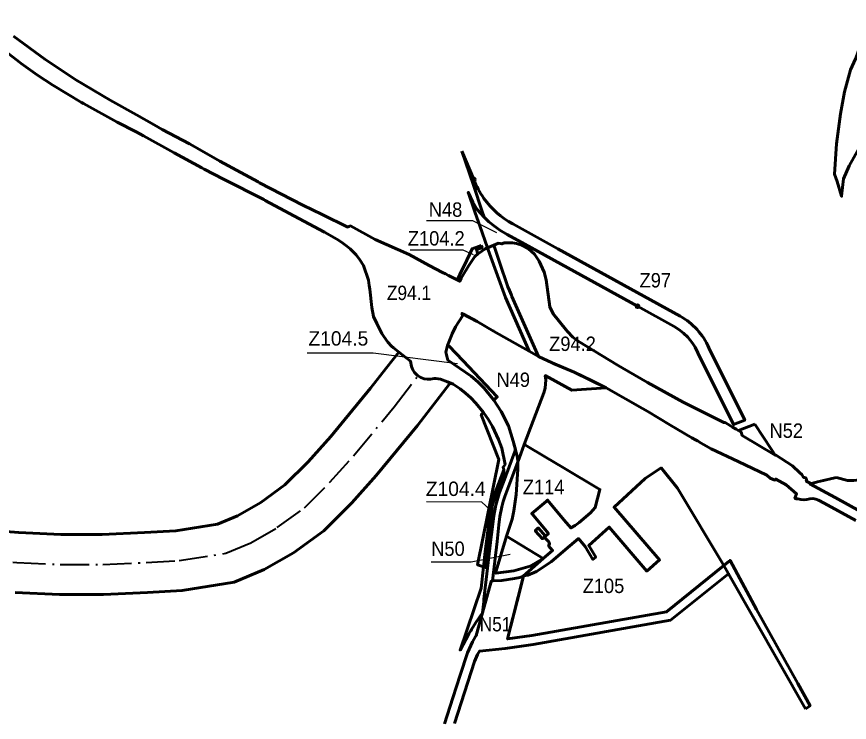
# Model space of a CAD drawing. Extents: x -650277 to -643425, y -1073980 to -1066720.
# Drawn here: x -647342 to -645952, y -1069308 to -1068130 of the extents above; entities that cross this region are included whole.
import ezdxf

# ---------------------------------------------------------------- set-up
doc = ezdxf.new("R2010")
doc.units = 0
doc.header["$LTSCALE"] = 9.6
doc.header["$PDMODE"] = 32
doc.header["$PDSIZE"] = 4.8
doc.linetypes.add('DOT_DASHED', pattern=[7.7, 5, -1.2, 0.3, -1.2])
for name, color, linetype, lineweight in [('15', 7, 'Continuous', 60), ('24', 7, 'Continuous', 60), ('30', 7, 'Continuous', 60), ('34', 7, 'Continuous', 60), ('36', 7, 'Continuous', 60), ('42', 7, 'Continuous', 60), ('48', 7, 'Continuous', 60), ('60', 7, 'Continuous', 60), ('62', 7, 'DOT_DASHED', 40), ('63', 7, 'Continuous', 25), ('7', 7, 'Continuous', 60)]:
    doc.layers.add(name, color=color, linetype=linetype, lineweight=lineweight)

msp = doc.modelspace()

# ---------------------------------------------------------------- linework, layer by layer
at = {"layer": '15'}
for points in [[(-646037.99, -1069242.88), (-646107, -1069119.41), (-646150.87, -1069037.64), (-646152.26, -1069038.76), (-646161.484, -1069046.228), (-646153.307, -1069059.947), (-646025.14, -1069285.394)], [(-646025.14, -1069285.394), (-646017.15, -1069280.19), (-646037.99, -1069242.88)]]:
    msp.add_lwpolyline(points, dxfattribs=at)
at = {"layer": '24'}
for points in [[(-646562.49, -1068790.69), (-646566.34, -1068794.32), (-646537.3, -1068868.95), (-646572.42, -1069044.94), (-646562.61, -1069048.08)], [(-646526.64, -1068877.47), (-646532.16, -1068850.47), (-646537.35, -1068835.56), (-646547.68, -1068814.22), (-646554.8, -1068801.98), (-646562.49, -1068790.69)], [(-646562.61, -1069048.08), (-646561.134, -1069035.627), (-646560.79, -1069032.72), (-646560.2, -1069027.69), (-646555.62, -1068988.63), (-646555, -1068983.32), (-646550.3, -1068943.27), (-646537.69, -1068909.82), (-646528.92, -1068886.55)], [(-646528.92, -1068886.55), (-646530.06, -1068882.16), (-646526.64, -1068877.47)], [(-646555.84, -1069050.22), (-646550.89, -1069007.7), (-646549.81, -1068998.88), (-646549.17, -1068993.71), (-646545.42, -1068963.3), (-646542.16, -1068945.12), (-646536.54, -1068925.95), (-646533.28, -1068917.17), (-646529.44, -1068906.81), (-646529.146, -1068895.373), (-646529.36, -1068895.94), (-646535.79, -1068912.99), (-646547.46, -1068943.97), (-646552.58, -1068987.63), (-646553.2, -1068992.9), (-646556.02, -1069016.97), (-646557.96, -1069033.47), (-646558.145, -1069035.029)], [(-646558.145, -1069035.029), (-646559.8, -1069048.98), (-646555.84, -1069050.22)]]:
    msp.add_lwpolyline(points, dxfattribs=at)
at = {"layer": '30'}
msp.add_line((-646583.49, -1068729.76), (-646571.91, -1068739.54), dxfattribs=at)
for points in [[(-646566.33, -1068512.04), (-646581.64, -1068517.24), (-646590.31, -1068536.69), (-646602.01, -1068560.15), (-646606.59, -1068569.33)], [(-646587.28, -1068545.28), (-646577.07, -1068530.2), (-646572.02, -1068526.07), (-646574.48, -1068518.75), (-646565.04, -1068515.86), (-646566.33, -1068512.04)], [(-646599.75, -1068566.49), (-646587.28, -1068545.28), (-646587.28, -1068545.28)], [(-646606.59, -1068569.33), (-646602.21, -1068571.5), (-646599.75, -1068566.49)], [(-646571.91, -1068739.54), (-646561.5, -1068750.22), (-646545.32, -1068769.89), (-646539.78, -1068764.65), (-646596.93, -1068704.15), (-646619.74, -1068680.15), (-646622.68, -1068678.75), (-646625.35, -1068689.7)], [(-646625.35, -1068689.7), (-646622.01, -1068703.3), (-646583.49, -1068729.76)]]:
    msp.add_lwpolyline(points, dxfattribs=at)
at = {"layer": '34'}
msp.add_lwpolyline([(-646161.484, -1069046.228), (-646238.632, -1068916.799), (-646266.118, -1068883.048), (-646277.268, -1068890.446), (-646292.75, -1068900.72), (-646344.49, -1068948.736), (-646268.528, -1069036.82), (-646290.099, -1069055.423), (-646352.71, -1068981.82), (-646386.936, -1069012.936), (-646375.346, -1069032.07), (-646379.973, -1069035.889), (-646393.09, -1069014.234), (-646404.269, -1069001.033), (-646425.52, -1069019.41), (-646449.418, -1069039.804), (-646474.13, -1069055.83), (-646488.537, -1069062.169), (-646495.89, -1069063.531), (-646500.995, -1069083.812), (-646522.35, -1069168.648), (-646482.211, -1069162.813), (-646256.824, -1069123.414)], close=True, dxfattribs=at)
at = {"layer": '36'}
msp.add_lwpolyline([(-646512.07, -1068954.68), (-646507.91, -1068927.47), (-646505.12, -1068885.31), (-646505.17, -1068872.78), (-646503.24, -1068867.61), (-646494.52, -1068844.29), (-646492.73, -1068845.01), (-646457.86, -1068865.8), (-646430.86, -1068881.89), (-646368.3, -1068919.19), (-646376.02, -1068949.34), (-646383.86, -1068958.24), (-646403.13, -1068974.41), (-646409.67, -1068979.3), (-646416.71, -1068983.21), (-646427.77, -1068970.39), (-646455.78, -1068936.87), (-646458.21, -1068938.99), (-646482.2, -1068959.52), (-646454.21, -1068992.73), (-646459.25, -1068996.98), (-646471.24, -1068983.41), (-646476.35, -1068987.98), (-646464.24, -1069001.49), (-646461.29, -1068998.81), (-646453.48, -1069006.75), (-646452.37, -1069010.01), (-646453.88, -1069013.1), (-646447.2, -1069020.9), (-646462.98, -1069034.61), (-646524, -1068997), (-646514.91, -1068968.48), (-646514.91, -1068968.48)], close=True, dxfattribs=at)
at = {"layer": '42'}
for points in [[(-646561.544, -1068464.842), (-646572.984, -1068451.81), (-646580.625, -1068439.803), (-646588.07, -1068422.96), (-646576.4, -1068457.27), (-646568.87, -1068479.14), (-646556.22, -1068515.84), (-646545.57, -1068511.42), (-646537.71, -1068508.16)], [(-646523.105, -1068493.54), (-646535.245, -1068486.342), (-646544.525, -1068479.79), (-646553.677, -1068472.283), (-646561.544, -1068464.842)], [(-646537.71, -1068508.16), (-646531.9, -1068509.25), (-646528.18, -1068507.58), (-646514.39, -1068507.56), (-646507.4, -1068508.45), (-646498.48, -1068511.26), (-646495.416, -1068512.888), (-646493.511, -1068509.855), (-646523.105, -1068493.54)], [(-646075.56, -1068861.95), (-646130.68, -1068829.21), (-646132.62, -1068823.54), (-646136.99, -1068820.88), (-646109.35, -1068810.23)], [(-646109.35, -1068810.23), (-646081.72, -1068852.51), (-646075.56, -1068861.95)], [(-646017.55, -1068909.75), (-646010.48, -1068907.86), (-646004.88, -1068906.5), (-645994.9, -1068904.1), (-645980.93, -1068900.85), (-645973.36, -1068898.93)], [(-645973.36, -1068898.93), (-645954.59, -1068904.41), (-645944.23, -1068904.13), (-645930.1, -1068902.47), (-645915.61, -1068901.02), (-645902.91, -1068901.43), (-645882.63, -1068905.88), (-645856.26, -1068997.79)], [(-645856.26, -1068997.79), (-645892.77, -1068977.86), (-645933.28, -1068955.74), (-645975.31, -1068932.8), (-646017.55, -1068909.75)]]:
    msp.add_lwpolyline(points, dxfattribs=at)
for points in [[(-646609.7, -1068647.84), (-646615.19, -1068659.11), (-646622.68, -1068678.75), (-646619.74, -1068680.15), (-646596.93, -1068704.15), (-646539.78, -1068764.65), (-646545.32, -1068769.89), (-646532.92, -1068788.95), (-646521.18, -1068812.95), (-646513.27, -1068838.37), (-646505.69, -1068865.56), (-646505.17, -1068872.78), (-646503.24, -1068867.61), (-646494.52, -1068844.29), (-646479.45, -1068804.37), (-646461.92, -1068757.93), (-646459.59, -1068750.19), (-646458.57, -1068736.31), (-646459.54, -1068728.94), (-646453.51, -1068732.3), (-646415.3, -1068753.62), (-646357.87, -1068749.64), (-646411.3, -1068723.11), (-646448.02, -1068707.99), (-646470.65, -1068697.38), (-646486.23, -1068688.54), (-646501.64, -1068679.81), (-646545.73, -1068654.81), (-646573.14, -1068638.98), (-646598.59, -1068625.34), (-646597.4, -1068628.74)], [(-646541.71, -1069054.76), (-646542, -1069059), (-646512, -1069055), (-646485, -1069047), (-646462.98, -1069034.61), (-646524, -1068997)]]:
    msp.add_lwpolyline(points, close=True, dxfattribs=at)
at = {"layer": '48'}
msp.add_lwpolyline([(-645874.15, -1068234.44), (-645917.44, -1068129.99), (-645938.87, -1068193.06), (-645941.41, -1068200.54), (-645949.52, -1068218.72), (-645959.76, -1068255.23), (-645966.56, -1068292.38), (-645973.25, -1068342.08), (-645976.63, -1068393.14), (-645971.94, -1068405.38), (-645964.53, -1068429.83), (-645963.12, -1068415.21), (-645961.7, -1068400.54), (-645952.21, -1068378.95), (-645926.06, -1068332.18), (-645883.87, -1068256.88), (-645880.28, -1068250.47), (-645872.64, -1068238.08)], close=True, dxfattribs=at)
at = {"layer": '60'}
msp.add_line((-646578.881, -1068401.54), (-646598.635, -1068354.436), dxfattribs=at)
for points in [[(-647419.713, -1068138.871), (-647405.71, -1068151.74), (-647372.38, -1068179.01), (-647337.74, -1068205.67), (-647334.62, -1068208.02), (-647307.39, -1068227.44), (-647281.64, -1068244.34), (-647234.11, -1068273.04), (-647230.83, -1068274.93), (-647174.56, -1068306.35), (-647142.788, -1068322.462), (-647130.29, -1068328.8), (-647079.16, -1068357.01), (-647032.91, -1068382.51), (-647029.23, -1068384.46), (-646997.06, -1068401.37), (-646929.56, -1068435.42), (-646927.06, -1068436.66)], [(-646634.37, -1068735.27), (-646622.62, -1068739.32), (-646613.44, -1068743.65), (-646601.86, -1068751.01), (-646592.53, -1068758.66), (-646583.98, -1068766.42), (-646575.28, -1068775.04), (-646562.49, -1068790.69), (-646554.8, -1068801.98), (-646547.68, -1068814.22), (-646537.35, -1068835.56), (-646532.16, -1068850.47), (-646526.64, -1068877.47), (-646530.06, -1068882.16), (-646528.92, -1068886.55), (-646529.44, -1068906.81), (-646510.56, -1068855.86), (-646509.323, -1068852.529), (-646513.27, -1068838.37), (-646521.18, -1068812.95), (-646532.92, -1068788.95), (-646545.32, -1068769.89), (-646561.5, -1068750.22), (-646571.91, -1068739.54), (-646583.49, -1068729.76), (-646622.01, -1068703.3), (-646625.35, -1068689.7), (-646622.68, -1068678.75), (-646615.19, -1068659.11), (-646609.7, -1068647.84), (-646597.4, -1068628.74), (-646596.28, -1068626.52), (-646596.28, -1068626.52), (-646573.14, -1068638.98), (-646545.73, -1068654.81), (-646545.73, -1068654.81), (-646501.64, -1068679.81), (-646486.23, -1068688.54), (-646526.1, -1068598.55), (-646555, -1068519.38), (-646555, -1068519.38), (-646556.22, -1068515.84), (-646559.72, -1068517.29), (-646569.61, -1068524.1), (-646572.02, -1068526.07), (-646577.07, -1068530.2), (-646587.28, -1068545.28), (-646599.75, -1068566.49), (-646602.21, -1068571.5), (-646606.59, -1068569.33), (-646620.94, -1068561.96), (-646625.86, -1068559.47), (-646631.18, -1068556.77), (-646653.21, -1068545.58), (-646686.84, -1068526.89), (-646686.84, -1068526.89), (-646743.69, -1068501.76), (-646785.05, -1068479.12), (-646787.55, -1068480.36), (-646789.49, -1068481.31), (-646832.29, -1068460.04), (-646864.48, -1068444.64), (-646936.47, -1068407.23), (-646938.95, -1068405.8), (-646967.64, -1068390), (-647002.71, -1068371.09), (-647040.77, -1068349.4), (-647044.93, -1068347.08), (-647053.75, -1068342.11), (-647099.2, -1068318.27), (-647112.813, -1068310.564), (-647142.41, -1068293.81), (-647186.26, -1068269.45), (-647243.39, -1068235.26), (-647246.8, -1068233.08), (-647295.47, -1068201.09), (-647347.74, -1068162.54)], [(-646598.635, -1068354.436), (-646579.62, -1068411.29), (-646564.78, -1068455.41), (-646561.544, -1068464.842)], [(-646927.06, -1068436.66), (-646854.18, -1068475.8), (-646828.2, -1068489.61), (-646807.82, -1068501.17), (-646799.79, -1068506.39), (-646790.66, -1068513.24), (-646785.34, -1068517.77), (-646779.93, -1068522.9), (-646775.44, -1068527.74), (-646768.95, -1068535.8), (-646763.1, -1068545.18), (-646754.92, -1068569.81), (-646753.35, -1068578.6), (-646752.59, -1068584.55), (-646749.35, -1068615.18), (-646746.32, -1068630.23), (-646740.91, -1068642.34), (-646735.62, -1068652.21), (-646732.25, -1068659.06), (-646729.34, -1068663.94), (-646722.6, -1068673.11), (-646716.39, -1068679.8), (-646716.39, -1068679.8), (-646712.93, -1068683), (-646684.7, -1068704.95), (-646682.98, -1068714.07), (-646680.88, -1068719.28), (-646678.08, -1068723.7), (-646673.16, -1068728.69), (-646667.17, -1068732.38), (-646667.17, -1068732.38), (-646661.5, -1068734.35), (-646656.47, -1068735.13), (-646651.21, -1068734.99), (-646645.18, -1068733.91), (-646642.04, -1068733.74), (-646634.37, -1068735.27)], [(-646561.544, -1068464.842), (-646553.677, -1068472.283), (-646544.525, -1068479.79), (-646535.245, -1068486.342), (-646523.105, -1068493.54), (-646493.511, -1068509.855), (-646305.678, -1068613.404)], [(-646234.342, -1068629.893), (-646234.342, -1068629.892), (-646438.626, -1068517.274), (-646513.45, -1068476.025), (-646513.567, -1068475.963)], [(-646337.93, -1068712.4), (-646404.83, -1068671.52), (-646413.45, -1068664.71), (-646422.32, -1068655.58), (-646425.11, -1068652.37), (-646446.54, -1068626.14), (-646451.82, -1068614.31), (-646458.03, -1068569.26), (-646461.14, -1068556.34), (-646469.51, -1068538.15), (-646477.41, -1068526.45), (-646487.92, -1068516.87), (-646498.48, -1068511.26), (-646507.4, -1068508.45), (-646514.39, -1068507.56), (-646528.18, -1068507.58), (-646531.9, -1068509.25), (-646537.71, -1068508.16), (-646545.57, -1068511.42), (-646541.06, -1068524.58), (-646535.84, -1068539.8), (-646521.81, -1068580.69), (-646519.14, -1068587.06), (-646516.07, -1068595.08), (-646515.09, -1068597.29), (-646470.65, -1068697.38), (-646448.02, -1068707.99), (-646444.51, -1068709.64), (-646411.3, -1068723.11), (-646380.94, -1068737.81), (-646357.87, -1068749.64), (-646297.08, -1068783.8), (-646288.37, -1068789.04), (-646251.73, -1068811.04), (-646214.92, -1068832.85), (-646208.7, -1068836.39), (-646205.48, -1068838.23), (-646199.24, -1068841.79), (-646195.52, -1068843.92), (-646182.57, -1068851.3)], [(-646305.678, -1068613.404), (-646243.997, -1068647.407), (-646236.707, -1068651.891), (-646228.691, -1068658.051), (-646221.348, -1068665.144), (-646213.659, -1068674.696), (-646209.179, -1068681.795), (-646204.654, -1068690.937), (-646145.083, -1068810.83), (-646126.317, -1068803.654), (-646186.371, -1068682.825)], [(-647344.902, -1069091.02), (-647270.522, -1069094.255), (-647197.498, -1069094.255), (-647123.648, -1069091.043), (-647065.688, -1069087.73), (-646978.92, -1069073.93), (-646929.186, -1069052.925), (-646880.163, -1069024.903), (-646829.104, -1068987.917), (-646782.784, -1068941.581), (-646741.85, -1068895.719), (-646673.05, -1068812.491), (-646618.655, -1068742.359), (-646617.991, -1068741.503), (-646622.62, -1068739.32), (-646634.37, -1068735.27), (-646642.04, -1068733.74), (-646645.18, -1068733.91), (-646651.21, -1068734.99), (-646656.47, -1068735.13), (-646661.5, -1068734.35), (-646667.17, -1068732.38), (-646673.16, -1068728.69), (-646678.08, -1068723.7), (-646680.88, -1068719.28), (-646682.98, -1068714.07), (-646684.7, -1068704.95), (-646704.316, -1068689.698), (-646725.374, -1068716.786), (-646751.116, -1068749.975), (-646817.718, -1068830.545), (-646855.506, -1068872.883), (-646894.206, -1068911.595), (-646934.465, -1068940.759), (-646973.61, -1068963.135), (-647006.63, -1068977.08), (-647076.422, -1068988.18), (-647128.674, -1068991.167), (-647199.672, -1068994.255), (-647268.348, -1068994.255), (-647338.816, -1068991.19), (-647417.895, -1068984.986)], [(-645933.28, -1068955.74), (-645975.31, -1068932.8), (-646017.55, -1068909.75), (-646017.39, -1068908.42), (-646023.56, -1068905.05), (-646023.13, -1068903.12), (-646023.92, -1068900.73), (-646025.57, -1068899.39), (-646028.18, -1068898.89), (-646031.31, -1068894.32), (-646034.65, -1068891.12), (-646046.48, -1068879.92), (-646074.78, -1068861.51), (-646075.56, -1068861.95), (-646130.68, -1068829.21), (-646132.62, -1068823.54), (-646136.99, -1068820.88), (-646140.73, -1068818.61), (-646146.85, -1068814.88), (-646150.26, -1068812.81), (-646159.1, -1068807.43), (-646161.45, -1068807.54), (-646229.44, -1068773.53), (-646288.59, -1068740.88), (-646331.26, -1068716.25), (-646337.93, -1068712.4)], [(-646182.57, -1068851.3), (-646137.23, -1068872.6), (-646089.63, -1068895.5), (-646084.1, -1068900.51), (-646076.09, -1068903.48), (-646074.51, -1068901.9), (-646057.13, -1068911.62), (-646039.84, -1068926.67), (-646042.5, -1068933.91), (-646040.65, -1068934.59), (-646037.5, -1068934.7), (-646032.61, -1068936.1), (-646027.69, -1068936.6), (-646022.77, -1068936.12), (-646017.6, -1068934.89), (-646012.64, -1068934.34), (-646007.7, -1068935.18), (-646002.95, -1068936.95), (-645993.5, -1068942.1), (-645940.77, -1068970.74)], [(-646505.17, -1068872.78), (-646526.81, -1068930.69), (-646530.08, -1068939.43), (-646532.13, -1068948), (-646535.13, -1068964.38), (-646537.02, -1068978.44), (-646539.77, -1069006.25)], [(-646524, -1068997), (-646514.91, -1068968.48), (-646514.91, -1068968.48), (-646512.07, -1068954.68), (-646507.91, -1068927.47), (-646505.12, -1068885.31), (-646505.17, -1068872.78)], [(-646462.98, -1069034.61), (-646485, -1069047), (-646512, -1069055), (-646542, -1069059), (-646541.71, -1069054.76), (-646524, -1068997)], [(-646539.77, -1069006.25), (-646539.77, -1069006.25), (-646547.412, -1069071.71)], [(-646547.412, -1069071.71), (-646532, -1069071), (-646511, -1069068), (-646502, -1069066), (-646496.317, -1069063.61), (-646462.98, -1069034.61)]]:
    msp.add_lwpolyline(points, dxfattribs=at)
msp.add_lwpolyline([(-646582.46, -1069152.81), (-646575.4, -1069141.46), (-646564.54, -1069125.08), (-646562.35, -1069106.21), (-646561.88, -1069102.18), (-646555.84, -1069050.22), (-646555.84, -1069050.22), (-646559.8, -1069048.98), (-646562.61, -1069048.08), (-646566.82, -1069083.62), (-646601.82, -1069187.25), (-646586.97, -1069160.06), (-646585.42, -1069157.56), (-646583.89, -1069155.1), (-646582.46, -1069152.81)], close=True, dxfattribs=at)
for centre, radius, start, end in [((-646447.332, -1068351.964), 140.58, 200.6496, 215.36619), ((-646447.332, -1068351.964), 140.58, 215.36631, 241.891), ((-646287.447, -1068726.224), 110, 23.23727, 61.13296)]:
    msp.add_arc(centre, radius, start, end, dxfattribs=at)
for p in [(-646578.881, -1068401.54), (-646305.678, -1068613.404)]:
    msp.add_point(p, dxfattribs=at)
at = {"layer": '62'}
msp.add_lwpolyline([(-647953.174, -1069007.503), (-647892.914, -1069003.305), (-647829.936, -1069000.155), (-647777.98, -1069001.73), (-647703.981, -1069006.455), (-647634.706, -1069014.33), (-647507.176, -1069026.93), (-647422.156, -1069034.805), (-647341.859, -1069041.105), (-647269.435, -1069044.255), (-647198.585, -1069044.255), (-647126.161, -1069041.105), (-647071.055, -1069037.955), (-646992.775, -1069025.505), (-646951.398, -1069008.03), (-646907.314, -1068982.831), (-646861.655, -1068949.756), (-646819.145, -1068907.232), (-646779.784, -1068863.132), (-646712.083, -1068781.233), (-646669.79, -1068726.705)], dxfattribs=at)
at = {"layer": '63'}
for points in [[(-646658, -1068470), (-646581, -1068470), (-646541, -1068490)], [(-646685, -1068519), (-646597, -1068519), (-646580, -1068527)], [(-646857, -1068691), (-646747, -1068691), (-646606, -1068709)], [(-646658, -1068939), (-646566, -1068940), (-646550, -1068955)], [(-646650, -1069040), (-646583, -1069040), (-646518, -1069027)]]:
    msp.add_lwpolyline(points, dxfattribs=at)
at = {"layer": '7'}
msp.add_lwpolyline([(-646611.107, -1069309.68), (-646577.878, -1069206.485), (-646572.586, -1069194.485), (-646569.114, -1069188.86), (-646526.31, -1069184.381), (-646479.84, -1069177.626), (-646250.409, -1069137.52), (-646153.307, -1069059.947), (-646161.484, -1069046.228), (-646256.824, -1069123.414), (-646482.211, -1069162.813), (-646522.35, -1069168.648), (-646495.89, -1069063.531), (-646496.317, -1069063.61), (-646496.317, -1069063.61), (-646502, -1069066), (-646511, -1069068), (-646532, -1069071), (-646547.412, -1069071.71), (-646549.91, -1069072.542), (-646564.54, -1069125.08), (-646564.605, -1069125.271), (-646574.978, -1069163.017), (-646574.978, -1069163.017), (-646574.33, -1069162.04), (-646575.87, -1069164.54), (-646581.29, -1069173.32), (-646589.56, -1069192.07), (-646601.41, -1069229.34), (-646613.6, -1069267.04), (-646627.59, -1069310.34)], dxfattribs=at)

# ---------------------------------------------------------------- texts
at = {"layer": '63'}
for s, width, p in [('N48', 0.95, (-646654, -1068464)), ('Z104.2', 0.95, (-646689, -1068512)), ('Z97', 0.95, (-646302, -1068582)), ('Z94.1', 0.9, (-646724, -1068603)), ('Z94.2', 0.95, (-646453, -1068688)), ('N49', 0.95, (-646541, -1068748)), ('N52', 0.95, (-646085, -1068833)), ('Z114', 0.95, (-646497, -1068927)), ('N50', 0.95, (-646650, -1069030)), ('Z105', 0.95, (-646397, -1069092)), ('N51', 0.9, (-646569, -1069156))]:
    msp.add_text(s, height=24, dxfattribs=dict(at, width=width)).set_placement(p)
for s, p in [('Z104.5', (-646855, -1068679)), ('Z104.4', (-646659, -1068930))]:
    msp.add_text(s, height=24, dxfattribs=at).set_placement(p)

doc.saveas('drawing.dxf')
